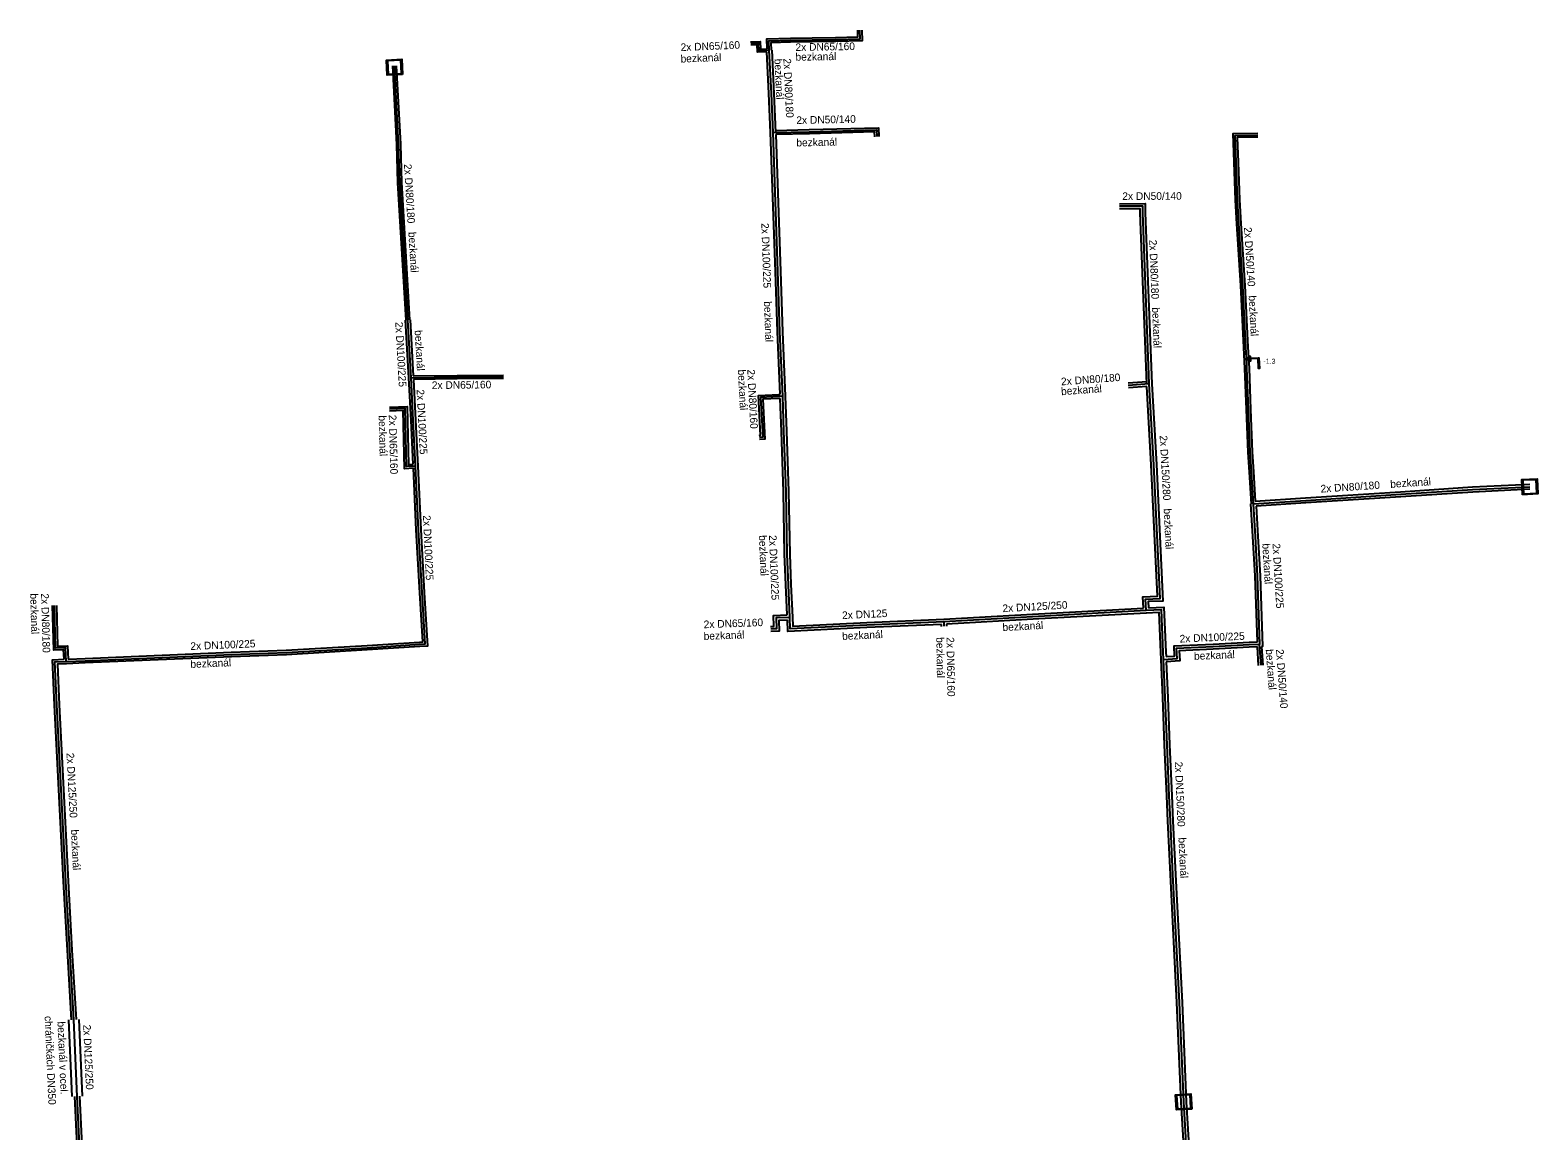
# Model space of a CAD drawing. Extents: x -606118 to -604472, y -1157869 to -1156854.
# Drawn here: x -606117.7 to -605820.8, y -1157340.8 to -1157124.1 of the extents above; entities that cross this region are included whole.
import ezdxf

# ---------------------------------------------------------------- set-up
doc = ezdxf.new("R2010")
doc.units = 0
for name, color, linetype in [('Osa trasy teplovodu', 7, 'Continuous'), ('Teplovod - trasa - okraj', 7, 'Continuous'), ('Teplovod - trasa popis', 7, 'Continuous'), ('Teplovod - trasa popis 2', 7, 'Continuous'), ('Teplovod - trasa popis 3', 7, 'Continuous'), ('výška krytí', 7, 'Continuous'), ('Výšková kóta trasy teplovodu', 7, 'Continuous'), ('Šachta trasy teplovodu', 7, 'Continuous')]:
    doc.layers.add(name, color=color, linetype=linetype)

msp = doc.modelspace()

# ---------------------------------------------------------------- linework, layer by layer
at = {"layer": 'Osa trasy teplovodu'}
for p, q in [((-606043.3, -1157181.13), (-606044.91, -1157154.07)), ((-605897.28, -1157193.69), (-605898.59, -1157160.01)), ((-606042.66, -1157192.49), (-606043.3, -1157181.13)), ((-605897.28, -1157193.69), (-605901.42, -1157194)), ((-605969.48, -1157196.12), (-605970.23, -1157196.17)), ((-605937.75, -1157240.54), (-605937.74, -1157241.43)), ((-605875.65, -1157244.97), (-605875.35, -1157249.1)), ((-606108.41, -1157333.99), (-606109.07, -1157318.9))]:
    msp.add_line(p, q, dxfattribs=at)
for points in [[(-605972.13, -1157127.99), (-605972.21, -1157126.13), (-605967.93, -1157126.05), (-605963.69, -1157125.98), (-605959.06, -1157125.87), (-605954.25, -1157125.75), (-605954.29, -1157124.06)], [(-605972.13, -1157127.99), (-605974.17, -1157128.08), (-605974.24, -1157126.6), (-605975.79, -1157126.67)], [(-605971.37, -1157144.2), (-605971.72, -1157136.52), (-605972.13, -1157127.99)], [(-606044.91, -1157154.07), (-606045.13, -1157146.53), (-606045.94, -1157131.07)], [(-605971.37, -1157144.2), (-605964.24, -1157144.04), (-605951.02, -1157143.67), (-605950.94, -1157145.01)], [(-605969.48, -1157196.12), (-605970.03, -1157183.44), (-605970.43, -1157171.52), (-605971.37, -1157144.2)], [(-605876.78, -1157217.31), (-605877.18, -1157211.04), (-605877.41, -1157207.11), (-605877.74, -1157198.74), (-605878.05, -1157190.63), (-605878.11, -1157189.53), (-605878.26, -1157186.52), (-605878.88, -1157174.34), (-605879.64, -1157162.14), (-605879.93, -1157157.5), (-605880.19, -1157150.06), (-605880.38, -1157144.8), (-605875.89, -1157144.72)], [(-605898.59, -1157160.01), (-605898.59, -1157158.71), (-605903.14, -1157158.73)], [(-606042.66, -1157192.49), (-606033.62, -1157192.38), (-606024.45, -1157192.32)], [(-606041.79, -1157209.89), (-606042.23, -1157200.86), (-606042.66, -1157192.49)], [(-605897.9, -1157238.35), (-605898.05, -1157236.09), (-605895.15, -1157235.97), (-605896.39, -1157209.61), (-605897.28, -1157193.69)], [(-605970.23, -1157196.17), (-605973.83, -1157196.36), (-605973.42, -1157204.2), (-605974.06, -1157204.26)], [(-605968.61, -1157227.23), (-605968.81, -1157214.91), (-605969.24, -1157203.03), (-605969.48, -1157196.12)], [(-606041.79, -1157209.89), (-606043.57, -1157209.99), (-606043.86, -1157198.56), (-606046.91, -1157198.66)], [(-606040.98, -1157244.98), (-606039.9, -1157244.9), (-606040.51, -1157234.78), (-606041.2, -1157222.42), (-606041.79, -1157209.89)], [(-605876.78, -1157217.31), (-605866.48, -1157216.66), (-605847.78, -1157215.42), (-605833.62, -1157214.5), (-605822.34, -1157213.95)], [(-605875.65, -1157244.97), (-605875.5, -1157244.96), (-605875.95, -1157231.49), (-605876.4, -1157223.73), (-605876.78, -1157217.31)], [(-605968.08, -1157239.68), (-605968.37, -1157233.25), (-605968.61, -1157227.23)], [(-606110.57, -1157248.36), (-606110.71, -1157245.66), (-606112.66, -1157245.74), (-606112.89, -1157237.33)], [(-605968.08, -1157239.68), (-605970.77, -1157239.78), (-605970.69, -1157241.9), (-605971.84, -1157241.95)], [(-605937.75, -1157240.54), (-605952.91, -1157241.18), (-605967.99, -1157241.91), (-605968.08, -1157239.68)], [(-605897.9, -1157238.35), (-605919.08, -1157239.49), (-605937.75, -1157240.54)], [(-605894.47, -1157247.94), (-605894.53, -1157246.53), (-605894.88, -1157238.19), (-605897.9, -1157238.35)], [(-606110.57, -1157248.36), (-606106.84, -1157248.2), (-606078.05, -1157246.99), (-606067.23, -1157246.57), (-606051.31, -1157245.64), (-606040.98, -1157244.98)], [(-605894.47, -1157247.94), (-605891.82, -1157247.75), (-605891.9, -1157245.76), (-605884.71, -1157245.44), (-605877.62, -1157245.04), (-605875.65, -1157244.97)], [(-606109.07, -1157318.9), (-606109.9, -1157305.2), (-606110.68, -1157291.65), (-606111.76, -1157269.72), (-606112.43, -1157256.92), (-606112.8, -1157248.45), (-606110.57, -1157248.36)], [(-605890.51, -1157335.08), (-605891.34, -1157315.5), (-605892.63, -1157290.3), (-605893.13, -1157279.76), (-605893.36, -1157274.79), (-605893.79, -1157264.79), (-605894.15, -1157255.46), (-605894.47, -1157247.94)], [(-606107.22, -1157359.44), (-606107.26, -1157357.98), (-606107.44, -1157355.35), (-606107.48, -1157354.68), (-606107.4, -1157354.2), (-606107.44, -1157353.61), (-606108.12, -1157340.88), (-606108.41, -1157333.99)], [(-605879.63, -1157378), (-605882.69, -1157372.34), (-605886.51, -1157363.58), (-605888.82, -1157356.57), (-605889.54, -1157351.26), (-605890.51, -1157335.08)]]:
    msp.add_lwpolyline(points, dxfattribs=at)
at = {"layer": 'Teplovod - trasa - okraj'}
for p, q in [((-606043.65, -1157181.15), (-606045.26, -1157154.1)), ((-606044.56, -1157154.05), (-606042.95, -1157181.11)), ((-605897.78, -1157193.71), (-605899.09, -1157160.03)), ((-605898.09, -1157159.99), (-605896.78, -1157193.67)), ((-606043.11, -1157192.52), (-606043.75, -1157181.16)), ((-606042.85, -1157181.1), (-606042.23, -1157192.14)), ((-605901.45, -1157193.5), (-605897.8, -1157193.22)), ((-605897.75, -1157194.22), (-605901.38, -1157194.5)), ((-605970.26, -1157195.77), (-605969.99, -1157195.75)), ((-605969.96, -1157196.55), (-605970.2, -1157196.57)), ((-605938.24, -1157241.44), (-605938.24, -1157241.06)), ((-605937.24, -1157241.01), (-605937.24, -1157241.42)), ((-605875.75, -1157249.13), (-605876.01, -1157245.48)), ((-605875.21, -1157245.45), (-605874.95, -1157249.07)), ((-606109.41, -1157334.03), (-606110.07, -1157318.94)), ((-606108.07, -1157318.85), (-606107.41, -1157333.94))]:
    msp.add_line(p, q, dxfattribs=at)
for points in [[(-605972.54, -1157127.71), (-605972.63, -1157125.73), (-605967.94, -1157125.65), (-605963.7, -1157125.58), (-605959.07, -1157125.47), (-605954.66, -1157125.36), (-605954.69, -1157124.07)], [(-605953.89, -1157124.05), (-605953.84, -1157126.14), (-605959.05, -1157126.27), (-605963.68, -1157126.38), (-605967.92, -1157126.45), (-605971.79, -1157126.52), (-605971.73, -1157127.97)], [(-605975.8, -1157126.37), (-605973.95, -1157126.29), (-605973.88, -1157127.77), (-605972.54, -1157127.71)], [(-605972.61, -1157128.31), (-605974.45, -1157128.4), (-605974.52, -1157126.91), (-605975.78, -1157126.97)], [(-605971.87, -1157144.23), (-605972.22, -1157136.55), (-605972.61, -1157128.31)], [(-605971.63, -1157127.97), (-605971.22, -1157136.5), (-605970.87, -1157144.18)], [(-606045.26, -1157154.09), (-606045.48, -1157146.55), (-606046.29, -1157131.09)], [(-606045.59, -1157131.06), (-606044.78, -1157146.52), (-606044.56, -1157154.06)], [(-605969.99, -1157195.75), (-605970.53, -1157183.46), (-605970.92, -1157171.54), (-605971.87, -1157144.22)], [(-605970.89, -1157143.79), (-605964.25, -1157143.64), (-605950.64, -1157143.26), (-605950.54, -1157144.99)], [(-605951.34, -1157145.03), (-605951.4, -1157144.08), (-605964.23, -1157144.44), (-605970.86, -1157144.59)], [(-605970.86, -1157144.59), (-605969.93, -1157171.5), (-605969.53, -1157183.42), (-605968.98, -1157196.09)], [(-605877.18, -1157217.34), (-605877.58, -1157211.06), (-605877.81, -1157207.13), (-605878.13, -1157198.76), (-605878.45, -1157190.64), (-605878.66, -1157186.54), (-605879.28, -1157174.36), (-605880.04, -1157162.17), (-605880.33, -1157157.52), (-605880.59, -1157150.07), (-605880.79, -1157144.41), (-605875.89, -1157144.32)], [(-605875.88, -1157145.12), (-605879.96, -1157145.19), (-605879.79, -1157150.04), (-605879.53, -1157157.48), (-605879.24, -1157162.12), (-605878.48, -1157174.32), (-605877.86, -1157186.5), (-605877.65, -1157190.61), (-605877.34, -1157198.73), (-605877.01, -1157207.09), (-605876.78, -1157211.01), (-605876.41, -1157216.79)], [(-605903.14, -1157158.23), (-605898.09, -1157158.21), (-605898.09, -1157160.01)], [(-605899.09, -1157160.01), (-605899.09, -1157159.21), (-605903.13, -1157159.23)], [(-606042.23, -1157192.14), (-606033.62, -1157192.03), (-606024.46, -1157191.97)], [(-606042.26, -1157209.52), (-606042.68, -1157200.88), (-606043.11, -1157192.52)], [(-606024.45, -1157192.67), (-606033.61, -1157192.73), (-606042.19, -1157192.84)], [(-606042.19, -1157192.84), (-606041.78, -1157200.84), (-606041.34, -1157209.87)], [(-605898.43, -1157237.88), (-605898.59, -1157235.62), (-605895.67, -1157235.5), (-605896.89, -1157209.64), (-605897.75, -1157194.22)], [(-605896.78, -1157193.66), (-605895.89, -1157209.58), (-605894.62, -1157236.45), (-605897.52, -1157236.57), (-605897.44, -1157237.82)], [(-606046.93, -1157198.26), (-606043.47, -1157198.14), (-606043.18, -1157209.57), (-606042.26, -1157209.52)], [(-605974.09, -1157203.86), (-605973.84, -1157203.83), (-605974.25, -1157195.99), (-605970.25, -1157195.77)], [(-605970.21, -1157196.57), (-605973.41, -1157196.74), (-605973, -1157204.57), (-605974.02, -1157204.65)], [(-605969.11, -1157227.24), (-605969.31, -1157214.93), (-605969.74, -1157203.05), (-605969.96, -1157196.55)], [(-605968.98, -1157196.1), (-605968.74, -1157203.01), (-605968.31, -1157214.9), (-605968.11, -1157227.22)], [(-606042.22, -1157210.32), (-606043.96, -1157210.41), (-606044.25, -1157198.97), (-606046.9, -1157199.06)], [(-606041.34, -1157209.87), (-606040.75, -1157222.4), (-606040.06, -1157234.75), (-606039.42, -1157245.32), (-606040.94, -1157245.43)], [(-606041.01, -1157244.53), (-606040.37, -1157244.49), (-606040.96, -1157234.81), (-606041.65, -1157222.44), (-606042.22, -1157210.32)], [(-605876.41, -1157216.79), (-605866.51, -1157216.16), (-605847.81, -1157214.93), (-605833.64, -1157214), (-605822.37, -1157213.45)], [(-605822.32, -1157214.44), (-605833.59, -1157215), (-605847.75, -1157215.92), (-605866.45, -1157217.15), (-605876.25, -1157217.78)], [(-605876.01, -1157244.48), (-605876.45, -1157231.52), (-605876.9, -1157223.76), (-605877.28, -1157217.34)], [(-605876.25, -1157217.78), (-605875.9, -1157223.7), (-605875.45, -1157231.47), (-605874.98, -1157245.44), (-605875.21, -1157245.45)], [(-605968.6, -1157239.2), (-605968.87, -1157233.28), (-605969.11, -1157227.25)], [(-605968.11, -1157227.21), (-605967.87, -1157233.23), (-605967.58, -1157239.66)], [(-606110.99, -1157247.92), (-606111.09, -1157246.08), (-606113.05, -1157246.16), (-606113.29, -1157237.34)], [(-606112.49, -1157237.32), (-606112.27, -1157245.33), (-606110.33, -1157245.25), (-606110.19, -1157247.89)], [(-605971.86, -1157241.45), (-605971.21, -1157241.42), (-605971.28, -1157239.3), (-605968.6, -1157239.2)], [(-605967.58, -1157239.66), (-605967.51, -1157241.39), (-605952.93, -1157240.68), (-605937.77, -1157240.04)], [(-605937.78, -1157240.04), (-605919.11, -1157238.99), (-605898.43, -1157237.88)], [(-605897.87, -1157238.85), (-605919.05, -1157239.99), (-605937.24, -1157241.01)], [(-605894.97, -1157247.96), (-605895.03, -1157246.55), (-605895.36, -1157238.72), (-605897.88, -1157238.85)], [(-605897.44, -1157237.82), (-605894.4, -1157237.67), (-605894.03, -1157246.51), (-605893.99, -1157247.4)], [(-605968.56, -1157240.2), (-605970.25, -1157240.26), (-605970.18, -1157242.38), (-605971.82, -1157242.45)], [(-605938.24, -1157241.06), (-605952.89, -1157241.68), (-605968.46, -1157242.44), (-605968.56, -1157240.2)], [(-606040.95, -1157245.43), (-606051.29, -1157246.09), (-606067.21, -1157247.02), (-606078.03, -1157247.44), (-606106.83, -1157248.65), (-606110.55, -1157248.81)], [(-606110.19, -1157247.89), (-606106.86, -1157247.75), (-606078.07, -1157246.54), (-606067.25, -1157246.12), (-606051.34, -1157245.19), (-606041, -1157244.53)], [(-605893.99, -1157247.4), (-605892.34, -1157247.29), (-605892.42, -1157245.28), (-605884.73, -1157244.94), (-605877.64, -1157244.54), (-605876.01, -1157244.48)], [(-605876.01, -1157245.48), (-605877.59, -1157245.54), (-605884.68, -1157245.94), (-605891.38, -1157246.24), (-605891.3, -1157248.22), (-605893.95, -1157248.4)], [(-606109.52, -1157318.93), (-606110.35, -1157305.22), (-606111.13, -1157291.67), (-606112.21, -1157269.74), (-606112.88, -1157256.94), (-606113.27, -1157248.02), (-606110.99, -1157247.92)], [(-606110.55, -1157248.81), (-606112.33, -1157248.88), (-606111.98, -1157256.89), (-606111.31, -1157269.69), (-606110.23, -1157291.62), (-606109.46, -1157305.17), (-606108.62, -1157318.87)], [(-605891.01, -1157335.1), (-605891.84, -1157315.53), (-605893.13, -1157290.32), (-605893.63, -1157279.78), (-605893.86, -1157274.81), (-605894.29, -1157264.81), (-605894.65, -1157255.48), (-605894.97, -1157247.96)], [(-605893.95, -1157248.4), (-605893.65, -1157255.44), (-605893.29, -1157264.77), (-605892.86, -1157274.77), (-605892.63, -1157279.73), (-605892.13, -1157290.27), (-605890.84, -1157315.48), (-605890.01, -1157335.05)], [(-606107.67, -1157359.46), (-606107.71, -1157358), (-606107.94, -1157354.66), (-606107.86, -1157354.18), (-606108.56, -1157340.9), (-606108.86, -1157334.01)], [(-606107.96, -1157333.97), (-606107.67, -1157340.85), (-606106.95, -1157354.22), (-606107.03, -1157354.7), (-606106.81, -1157357.96), (-606106.77, -1157359.41)], [(-605880.28, -1157377.85), (-605883.14, -1157372.56), (-605886.98, -1157363.75), (-605889.31, -1157356.68), (-605890.03, -1157351.31), (-605891.01, -1157335.1)], [(-605890.01, -1157335.05), (-605889.04, -1157351.22), (-605888.33, -1157356.45), (-605886.05, -1157363.4), (-605882.24, -1157372.13), (-605879.19, -1157377.77)]]:
    msp.add_lwpolyline(points, dxfattribs=at)
at = {"layer": 'Výšková kóta trasy teplovodu'}
msp.add_lwpolyline([(-605877.37, -1157188.8), (-605877.35, -1157189.2), (-605878.15, -1157188.77), (-605877.4, -1157188.26), (-605877.38, -1157188.65), (-605875.78, -1157188.57), (-605875.78, -1157188.57), (-605875.69, -1157188.57), (-605875.59, -1157190.65), (-605875.76, -1157190.65), (-605875.85, -1157188.73), (-605877.37, -1157188.8)], dxfattribs=at)
at = {"layer": 'Šachta trasy teplovodu'}
for points in [[(-606044.34, -1157132.79), (-606047.35, -1157132.94), (-606047.5, -1157129.94), (-606044.5, -1157129.78), (-606044.34, -1157132.79)], [(-606044.68, -1157129.98), (-606047.31, -1157130.12), (-606047.17, -1157132.75), (-606044.54, -1157132.61), (-606044.68, -1157129.98)], [(-605823.77, -1157215.52), (-605823.92, -1157212.52), (-605820.92, -1157212.37), (-605820.77, -1157215.37), (-605823.77, -1157215.52)], [(-605820.97, -1157215.19), (-605821.1, -1157212.56), (-605823.72, -1157212.69), (-605823.59, -1157215.32), (-605820.97, -1157215.19)], [(-605888.92, -1157336.49), (-605891.92, -1157336.67), (-605892.1, -1157333.67), (-605889.1, -1157333.49), (-605888.92, -1157336.49)], [(-605889.27, -1157333.68), (-605891.9, -1157333.84), (-605891.74, -1157336.47), (-605889.12, -1157336.31), (-605889.27, -1157333.68)]]:
    msp.add_lwpolyline(points, dxfattribs=at)

# ---------------------------------------------------------------- texts
at = {"layer": 'Teplovod - trasa popis'}
for s, rotation, p in [('2x DN65/160', 2.3991, (-605989.56, -1157128.18)), ('2x DN65/160', 0.9991, (-605966.95, -1157128.16)), ('2x DN80/180', 272.6739, (-605969.35, -1157129.65)), ('2x DN50/140', 1.2931, (-605966.78, -1157142.54)), ('2x DN80/180', 273.414, (-606044.07, -1157150.45)), ('2x DN50/140', 0.2351, (-605902.6, -1157157.49)), ('2x DN100/225', 271.9836, (-605973.7, -1157162.06)), ('2x DN80/180', 272.2159, (-605897.31, -1157165.35)), ('2x DN50/140', 273.5693, (-605878.63, -1157162.89)), ('2x DN100/225', 273.2358, (-606045.79, -1157181.54)), ('2x DN80/160', 272.9713, (-605976.46, -1157190.89)), ('2x DN80/180', 4.3064, (-605914.61, -1157194)), ('2x DN100/225', 272.9073, (-606041.58, -1157194.83)), ('2x DN65/160', 0.7155, (-606038.57, -1157194.72)), ('2x DN65/160', 271.4532, (-606047.06, -1157199.81)), ('2x DN150/280', 273.2069, (-605895.25, -1157203.88)), ('2x DN80/180', 3.769, (-605863.51, -1157215.11)), ('2x DN100/225', 272.6962, (-606040.34, -1157219.59)), ('2x DN100/225', 272.3343, (-605972.19, -1157223.51)), ('2x DN100/225', 273.3356, (-605873.02, -1157225.15)), ('2x DN80/180', 271.5411, (-606115.53, -1157234.97)), ('2x DN125/250', 3.2278, (-605926.16, -1157238.66)), ('2x DN65/160', 2.1618, (-605985.02, -1157241.82)), ('2x DN125', 2.777, (-605957.75, -1157240.02)), ('2x DN100/225', 2.5271, (-605891.28, -1157244.64)), ('2x DN100/225', 2.4046, (-606086.1, -1157246.1)), ('2x DN65/160', 270.8782, (-605937.22, -1157243.58)), ('2x DN50/140', 274.1757, (-605872.33, -1157245.99)), ('2x DN125/250', 272.9875, (-606110.54, -1157266.39)), ('2x DN150/280', 272.4561, (-605892.26, -1157268.11)), ('2x DN125/250', 272.5132, (-606107.25, -1157319.89))]:
    msp.add_text(s, height=1.5, rotation=rotation, dxfattribs=at).set_placement(p)
at = {"layer": 'Teplovod - trasa popis 2'}
for s, rotation, p in [('bezkanál', 2.3991, (-605989.56, -1157130.45)), ('bezkanál', 272.6996, (-605971.12, -1157129.72)), ('bezkanál', 0.9991, (-605966.95, -1157130.08)), ('bezkanál', 1.2931, (-605966.78, -1157146.96)), ('bezkanál', 273.414, (-606043.2, -1157163.82)), ('bezkanál', 271.8927, (-605973.16, -1157177.45)), ('bezkanál', 272.8889, (-605877.72, -1157176.32)), ('bezkanál', 272.2159, (-605896.74, -1157178.65)), ('bezkanál', 273.2358, (-606041.96, -1157183.15)), ('bezkanál', 272.9713, (-605978.32, -1157190.91)), ('bezkanál', 4.3064, (-605914.61, -1157195.94)), ('bezkanál', 271.4532, (-606049.06, -1157199.92)), ('bezkanál', 3.769, (-605849.79, -1157214.19)), ('bezkanál', 272.7012, (-605894.45, -1157218.27)), ('bezkanál', 272.3343, (-605974.17, -1157223.51)), ('bezkanál', 273.3356, (-605875.03, -1157225.15)), ('bezkanál', 271.5411, (-606117.68, -1157234.97)), ('bezkanál', 2.1618, (-605985.02, -1157244.12)), ('bezkanál', 2.777, (-605957.75, -1157244.13)), ('bezkanál', 3.2278, (-605926.16, -1157242.39)), ('bezkanál', 270.8782, (-605939.23, -1157243.58)), ('bezkanál', 2.4046, (-606086.1, -1157249.64)), ('bezkanál', 2.5271, (-605888.45, -1157248.05)), ('bezkanál', 274.1757, (-605874.36, -1157245.99)), ('bezkanál', 272.8091, (-606109.66, -1157281.47)), ('bezkanál', 272.6829, (-605891.55, -1157283.04)), ('bezkanál v ocel.', 272.5132, (-606112.31, -1157319.27))]:
    msp.add_text(s, height=1.5, rotation=rotation, dxfattribs=at).set_placement(p)
at = {"layer": 'Teplovod - trasa popis 3'}
msp.add_text('chráničkách DN350', height=1.5, rotation=272.5132, dxfattribs=at).set_placement((-606114.84, -1157318.19))
at = {"layer": 'výška krytí'}
msp.add_text('-1.3', height=1, dxfattribs=at).set_placement((-605874.81, -1157189.75))

doc.saveas('drawing.dxf')
